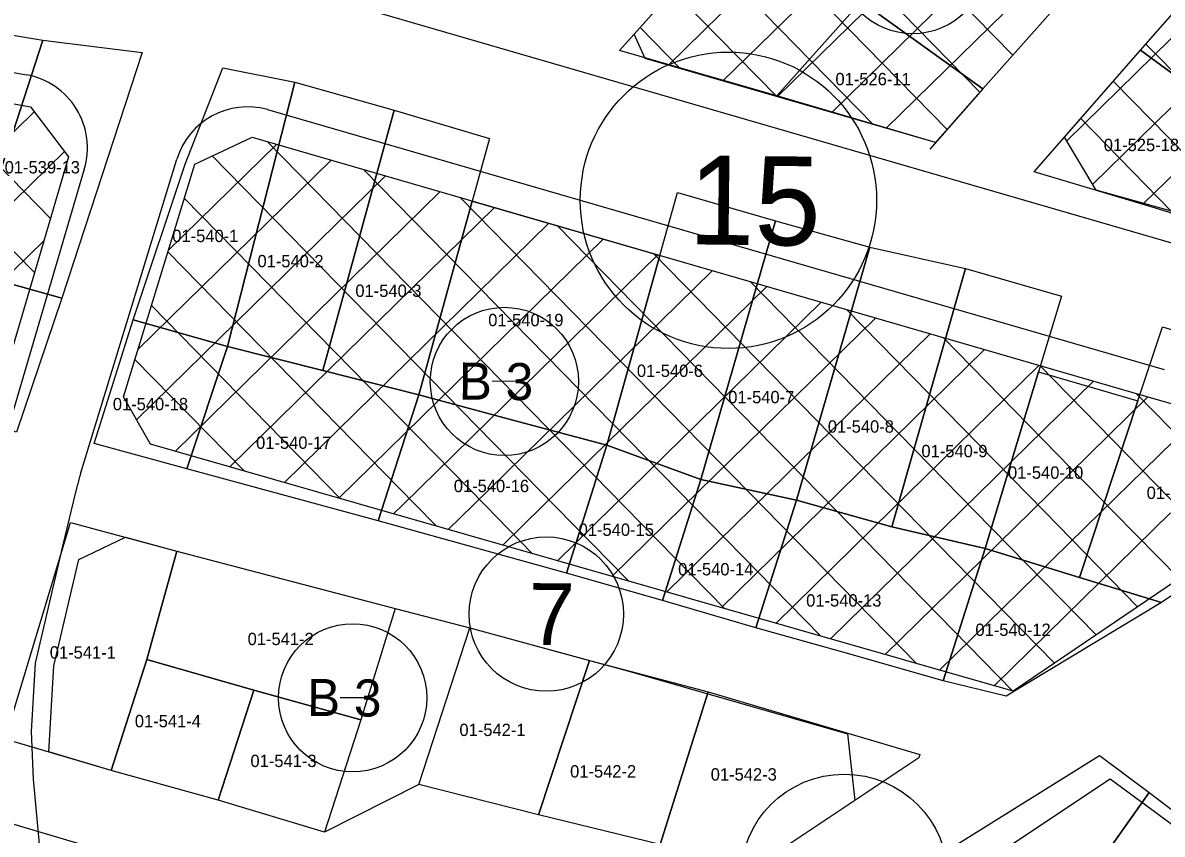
# Model space of a CAD drawing. Extents: x 413946 to 415528, y 4453939 to 4454944.
# Drawn here: x 415176.9 to 415269.2, y 4454344.2 to 4454409.9 of the extents above; entities that cross this region are included whole.
import ezdxf

# ---------------------------------------------------------------- set-up
doc = ezdxf.new("R2010")
doc.units = 0
for name, color, linetype in [('0_KADASTRO', 7, 'Continuous'), ('Level 27', 7, 'Continuous'), ('Level 28', 7, 'Continuous'), ('Level 29', 7, 'Continuous'), ('Level 32', 7, 'Continuous'), ('Level 34', 7, 'Continuous'), ('Level 58', 7, 'Continuous'), ('Level 62', 7, 'Continuous')]:
    doc.layers.add(name, color=color, linetype=linetype)

msp = doc.modelspace()

# ---------------------------------------------------------------- linework, layer by layer
at = {"layer": '0_KADASTRO'}
for points in [[(415225.23, 4454407.64), (415234.94, 4454418.45), (415244.8, 4454411.6), (415237.99, 4454403.96)], [(415244.8, 4454411.6), (415251.43, 4454419.09), (415251.62, 4454419.3), (415261.25, 4454411.96), (415254.68, 4454404.53)], [(415267.45, 4454407.66), (415274.07, 4454415.22), (415283.75, 4454408.21), (415280.79, 4454405.04), (415279.76, 4454403.95), (415277.28, 4454400.45), (415274.74, 4454402.31)], [(415237.99, 4454403.96), (415244.8, 4454411.6), (415254.68, 4454404.53), (415250.84, 4454400.18)], [(415164.81, 4454392.51), (415170.55, 4454409.79), (415178.51, 4454408.47), (415172.41, 4454389.72)], [(415172.41, 4454389.72), (415178.51, 4454408.47), (415186.56, 4454407.48), (415180.05, 4454387.58)], [(415258.83, 4454397.82), (415267.45, 4454407.66), (415274.74, 4454402.31), (415277.28, 4454400.45), (415274.26, 4454396.92), (415271.72, 4454393.93), (415268.37, 4454394.95)], [(415185.83, 4454385.83), (415190.04, 4454398.42), (415193.1, 4454406.23), (415198.93, 4454405.07), (415193.48, 4454383.68)], [(415193.48, 4454383.68), (415198.93, 4454405.07), (415206.97, 4454402.8), (415201.2, 4454381.72)], [(415201.2, 4454381.72), (415206.97, 4454402.8), (415214.7, 4454400.5), (415213.302, 4454395.439), (415208.97, 4454379.75)], [(415208.97, 4454379.75), (415213.302, 4454395.439), (415220.87, 4454393.25), (415228.514, 4454391.039), (415224.21, 4454375.67), (415216.6, 4454377.69)], [(415224.21, 4454375.67), (415228.514, 4454391.039), (415229.94, 4454396.13), (415237.87, 4454393.84), (415231.83, 4454372.91)], [(415231.83, 4454372.91), (415237.87, 4454393.84), (415245.51, 4454391.7), (415239.56, 4454371.23)], [(415239.56, 4454371.23), (415245.51, 4454391.7), (415253.27, 4454389.97), (415247.29, 4454369.07)], [(415247.29, 4454369.07), (415253.27, 4454389.97), (415261.03, 4454387.75), (415259.18, 4454381.61), (415254.85, 4454367.31)], [(415168.83, 4454378.8), (415172.41, 4454389.72), (415180.05, 4454387.58), (415176.39, 4454376.74)], [(415182.67, 4454375.82), (415185.83, 4454385.83), (415193.48, 4454383.68), (415190.2, 4454373.75)], [(415262.5, 4454364.97), (415267.23, 4454379.26), (415269.22, 4454385.27), (415282.582, 4454381.146), (415285.81, 4454380.15), (415289.82, 4454376.75), (415276.237, 4454367.69), (415269.13, 4454362.95)], [(415190.2, 4454373.75), (415193.48, 4454383.68), (415201.2, 4454381.72), (415208.97, 4454379.75), (415205.69, 4454369.54)], [(415254.85, 4454367.31), (415259.18, 4454381.61), (415267.23, 4454379.26), (415262.5, 4454364.97)], [(415205.69, 4454369.54), (415208.97, 4454379.75), (415216.6, 4454377.69), (415224.21, 4454375.67), (415220.95, 4454365.32)], [(415220.95, 4454365.32), (415224.21, 4454375.67), (415231.83, 4454372.91), (415228.73, 4454363.11)], [(415228.73, 4454363.11), (415231.83, 4454372.91), (415239.56, 4454371.23), (415236.29, 4454360.89)], [(415236.29, 4454360.89), (415239.56, 4454371.23), (415247.29, 4454369.07), (415254.85, 4454367.31), (415251.46, 4454356.59), (415244.01, 4454358.74)], [(415175.48, 4454351.88), (415180.77, 4454369.43), (415189.39, 4454367.1), (415186.95, 4454358.32), (415184.05, 4454349.35)], [(415186.95, 4454358.32), (415189.39, 4454367.1), (415207.06, 4454362.45), (415204.29, 4454353.43), (415195.61, 4454355.85)], [(415251.46, 4454356.59), (415254.85, 4454367.31), (415262.5, 4454364.97), (415269.13, 4454362.95), (415256.56, 4454355.35)], [(415208.98, 4454348.2), (415213.12, 4454360.9), (415222.81, 4454358.25), (415218.68, 4454345.75)], [(415184.05, 4454349.35), (415186.95, 4454358.32), (415195.61, 4454355.85), (415192.72, 4454346.93)], [(415218.68, 4454345.75), (415222.81, 4454358.25), (415232.41, 4454355.7), (415228.54, 4454343.35)], [(415192.72, 4454346.93), (415195.61, 4454355.85), (415204.29, 4454353.43), (415201.34, 4454344.36)], [(415228.54, 4454343.35), (415232.41, 4454355.7), (415249.56, 4454350.64), (415249.48, 4454350.36), (415234.67, 4454340.5)], [(415250.984, 4454342.38), (415264.123, 4454350.547), (415264.2, 4454350.49), (415268.14, 4454347.57), (415265.14, 4454343.31), (415263.86, 4454341.48), (415262.46, 4454339.35), (415259.73, 4454335.58), (415258.68, 4454336.397), (415251.73, 4454341.8)], [(415259.73, 4454335.58), (415262.46, 4454339.35), (415263.86, 4454341.48), (415265.14, 4454343.31), (415268.14, 4454347.57), (415275.96, 4454341.63), (415271.42, 4454334.96), (415270.31, 4454333.38), (415267.64, 4454329.34), (415265.69, 4454330.906), (415263.32, 4454332.81)], [(415170.03, 4454333.38), (415173.69, 4454345.73), (415181.44, 4454343.44), (415177.6, 4454331.01), (415171.68, 4454332.9)]]:
    msp.add_lwpolyline(points, close=True, dxfattribs=at)
at = {"layer": 'Level 27'}
for p, q in [((415204.089, 4454370.927), (415187.252, 4454375.747)), ((415204.09, 4454370.927), (415204.089, 4454370.927)), ((415204.092, 4454370.927), (415204.091, 4454370.927)), ((415257.121, 4454355.751), (415204.092, 4454370.927))]:
    msp.add_line(p, q, dxfattribs=at)
for points in [[(415226.413, 4454408.957), (415234.94, 4454418.45), (415241.61, 4454426.04), (415248.27, 4454433.38), (415254.93, 4454441.05), (415261.53, 4454448.35), (415268.31, 4454455.75), (415274.51, 4454462.72), (415280.65, 4454469.3), (415288.33, 4454477.82), (415292.88, 4454482.84)], [(415310.574, 4454466.789), (415305.2, 4454460.96), (415299.8, 4454455.11), (415293.06, 4454447.82), (415287.9, 4454441.92), (415281.11, 4454434.3), (415274.64, 4454426.85), (415267.96, 4454419.45), (415261.25, 4454411.96), (415254.68, 4454404.53), (415250.364, 4454399.64)], [(415261.285, 4454400.622), (415267.45, 4454407.66), (415274.07, 4454415.22), (415280.63, 4454422.65), (415287.22, 4454430.12), (415292.45, 4454436.24), (415293.926, 4454437.825), (415294.498, 4454437.407), (415302.032, 4454445.623), (415316.534, 4454461.44)], [(415185.225, 4454368.226), (415189.39, 4454367.1), (415207.06, 4454362.45), (415213.12, 4454360.9), (415226.002, 4454357.377)], [(415201.34, 4454344.36), (415192.72, 4454346.93), (415184.05, 4454349.35), (415178.995, 4454350.842)], [(415264.984, 4454348.669), (415274.805, 4454341.419), (415313.615, 4454312.821), (415331.254, 4454309.711), (415373.854, 4454288.964), (415353.123, 4454256.024)], [(415234.67, 4454340.5), (415228.54, 4454343.35), (415218.68, 4454345.75), (415208.98, 4454348.2)]]:
    msp.add_lwpolyline(points, dxfattribs=at)
at = {"layer": 'Level 28'}
msp.add_line((415278.268, 4454370.094), (415257.121, 4454355.751), dxfattribs=at)
for points in [[(415250.84, 4454400.18), (415227.323, 4454406.996), (415226.413, 4454408.957)], [(415195.475, 4454400.608), (415268.668, 4454379.396)], [(415284.734, 4454390.491), (415263.836, 4454396.314), (415261.285, 4454400.622)], [(415187.252, 4454375.747), (415185.051, 4454379.589), (415190.823, 4454398.431)], [(415268.668, 4454379.396), (415279.451, 4454376.391)], [(415178.995, 4454350.842), (415179.408, 4454357.806), (415181.446, 4454366.435), (415185.225, 4454368.226)], [(415243.716, 4454352.307), (415244.306, 4454346.915)], [(415242.176, 4454333.483), (415264.984, 4454348.669)]]:
    msp.add_lwpolyline(points, dxfattribs=at)
at = {"layer": 'Level 29'}
for p, q in [((415177.519, 4454403.064), (415180.61, 4454399.019)), ((415190.823, 4454398.431), (415195.475, 4454400.608)), ((415226.002, 4454357.377), (415243.716, 4454352.307)), ((415208.98, 4454348.2), (415201.34, 4454344.36))]:
    msp.add_line(p, q, dxfattribs=at)
for points in [[(415078.7, 4454427.908), (415121.68, 4454415.05), (415144.9, 4454408.93), (415177.519, 4454403.064)], [(415180.61, 4454399.019), (415173.461, 4454374.818), (415172.452, 4454371.283)], [(415244.306, 4454346.915), (415234.67, 4454340.5)]]:
    msp.add_lwpolyline(points, dxfattribs=at)
at = {"layer": 'Level 32'}
for p, q in [((415216.91, 4454380.829), (415214.91, 4454380.85)), ((415204.62, 4454355.215), (415202.62, 4454355.235))]:
    msp.add_line(p, q, dxfattribs=at)
for centre in [(415248.986, 4454414.989), (415215.91, 4454380.84), (415203.62, 4454355.225)]:
    msp.add_circle(centre, 6, dxfattribs=at)
at = {"layer": 'Level 34'}
for p, q in [((415229.199, 4454406.452), (415253.156, 4454429.923)), ((415233.61, 4454405.174), (415256.475, 4454427.575)), ((415238.021, 4454403.895), (415259.794, 4454425.227)), ((415257.092, 4454407.258), (415240.229, 4454424.469)), ((415242.432, 4454402.617), (415263.113, 4454422.879)), ((415254.436, 4454404.253), (415237.581, 4454421.456)), ((415246.843, 4454401.339), (415266.432, 4454420.531)), ((415261.458, 4454400.33), (415282.722, 4454421.164)), ((415251.781, 4454401.247), (415234.933, 4454418.443)), ((415263.556, 4454396.786), (415286.036, 4454418.81)), ((415267.693, 4454395.239), (415289.349, 4454416.457)), ((415245.793, 4454401.643), (415232.255, 4454415.461)), ((415237.973, 4454403.909), (415229.577, 4454412.479)), ((415230.152, 4454406.176), (415226.898, 4454409.497)), ((415284.946, 4454390.737), (415267.882, 4454408.154)), ((415177.843, 4454389.651), (415161.96, 4454405.862)), ((415179.14, 4454394.043), (415168.757, 4454404.639)), ((415277.655, 4454392.464), (415265.239, 4454405.136)), ((415154.868, 4454380.177), (415177.823, 4454402.666)), ((415269.952, 4454394.61), (415262.596, 4454402.118)), ((415188.678, 4454391.429), (415197.46, 4454400.033)), ((415225.678, 4454370.685), (415196.712, 4454400.249)), ((415159.284, 4454378.905), (415180.269, 4454399.465)), ((415220.017, 4454370.748), (415192.242, 4454399.095)), ((415186.227, 4454383.428), (415201.87, 4454398.755)), ((415186.12, 4454377.723), (415206.282, 4454397.477)), ((415231.341, 4454370.621), (415204.532, 4454397.984)), ((415189.238, 4454375.179), (415210.692, 4454396.198)), ((415214.354, 4454370.812), (415189.982, 4454395.686)), ((415237.003, 4454370.557), (415212.353, 4454395.717)), ((415193.662, 4454373.913), (415215.103, 4454394.92)), ((415198.085, 4454372.647), (415219.514, 4454393.642)), ((415242.665, 4454370.494), (415220.173, 4454393.451)), ((415163.701, 4454377.633), (415178.606, 4454392.235)), ((415202.509, 4454371.381), (415223.925, 4454392.363)), ((415208.692, 4454370.876), (415188.649, 4454391.333)), ((415207.72, 4454370.887), (415228.336, 4454391.085)), ((415248.328, 4454370.43), (415227.994, 4454391.184)), ((415213.371, 4454370.823), (415232.747, 4454389.807)), ((415253.99, 4454370.367), (415235.814, 4454388.918)), ((415219.021, 4454370.76), (415237.157, 4454388.528)), ((415224.672, 4454370.696), (415241.568, 4454387.25)), ((415202.632, 4454371.345), (415187.315, 4454386.979)), ((415259.652, 4454370.303), (415243.635, 4454386.651)), ((415230.323, 4454370.633), (415245.979, 4454385.972)), ((415235.974, 4454370.569), (415250.39, 4454384.693)), ((415265.314, 4454370.239), (415251.455, 4454384.385)), ((415241.625, 4454370.506), (415254.801, 4454383.415)), ((415194.85, 4454373.573), (415185.981, 4454382.625)), ((415247.275, 4454370.442), (415259.212, 4454382.137)), ((415270.977, 4454370.176), (415259.276, 4454382.118)), ((415252.927, 4454370.378), (415263.623, 4454380.858)), ((415276.639, 4454370.112), (415267.096, 4454379.851)), ((415258.577, 4454370.315), (415268.033, 4454379.58)), ((415264.228, 4454370.251), (415272.478, 4454378.334)), ((415206.932, 4454370.115), (415207.72, 4454370.887)), ((415207.72, 4454370.887), (415207.72, 4454370.887)), ((415207.72, 4454370.887), (415207.72, 4454370.887)), ((415207.72, 4454370.887), (415207.72, 4454370.887)), ((415208.692, 4454370.876), (415208.692, 4454370.876)), ((415208.692, 4454370.876), (415208.692, 4454370.876)), ((415208.692, 4454370.876), (415208.692, 4454370.876)), ((415210.414, 4454369.118), (415208.692, 4454370.876)), ((415211.356, 4454368.849), (415213.371, 4454370.823)), ((415218.196, 4454366.891), (415214.354, 4454370.812)), ((415215.779, 4454367.583), (415219.021, 4454370.76)), ((415219.021, 4454370.76), (415219.021, 4454370.76)), ((415219.021, 4454370.76), (415219.021, 4454370.76)), ((415219.021, 4454370.76), (415219.021, 4454370.76)), ((415220.017, 4454370.748), (415220.017, 4454370.748)), ((415220.017, 4454370.748), (415220.017, 4454370.748)), ((415225.978, 4454364.664), (415220.017, 4454370.748)), ((415220.203, 4454366.317), (415224.672, 4454370.696)), ((415224.626, 4454365.051), (415230.323, 4454370.633)), ((415233.759, 4454362.437), (415225.678, 4454370.685)), ((415229.05, 4454363.785), (415235.974, 4454370.569)), ((415230.323, 4454370.633), (415230.323, 4454370.633)), ((415230.323, 4454370.633), (415230.323, 4454370.633)), ((415230.323, 4454370.633), (415230.323, 4454370.633)), ((415241.541, 4454360.21), (415231.341, 4454370.621)), ((415233.473, 4454362.519), (415241.625, 4454370.506)), ((415237.003, 4454370.557), (415237.003, 4454370.557)), ((415237.003, 4454370.557), (415237.003, 4454370.557)), ((415249.323, 4454357.983), (415237.003, 4454370.557)), ((415237.896, 4454361.253), (415247.275, 4454370.442)), ((415241.625, 4454370.506), (415241.625, 4454370.506)), ((415241.625, 4454370.506), (415241.625, 4454370.506)), ((415241.625, 4454370.506), (415241.625, 4454370.506)), ((415257.105, 4454355.756), (415242.665, 4454370.494)), ((415260.479, 4454358.028), (415248.328, 4454370.43)), ((415242.32, 4454359.987), (415252.927, 4454370.378)), ((415246.743, 4454358.721), (415258.577, 4454370.315)), ((415251.167, 4454357.455), (415264.228, 4454370.251)), ((415252.927, 4454370.378), (415252.927, 4454370.378)), ((415252.927, 4454370.378), (415252.927, 4454370.378)), ((415253.99, 4454370.367), (415253.99, 4454370.367)), ((415253.99, 4454370.367), (415253.99, 4454370.367)), ((415253.99, 4454370.367), (415253.99, 4454370.367)), ((415263.843, 4454360.31), (415253.99, 4454370.367)), ((415255.59, 4454356.189), (415269.879, 4454370.188)), ((415267.207, 4454362.591), (415259.652, 4454370.303)), ((415264.228, 4454370.251), (415264.228, 4454370.251)), ((415264.228, 4454370.251), (415264.228, 4454370.251)), ((415265.314, 4454370.239), (415265.314, 4454370.239)), ((415265.314, 4454370.239), (415265.314, 4454370.239)), ((415270.572, 4454364.873), (415265.314, 4454370.239))]:
    msp.add_line(p, q, dxfattribs=at)
at = {"layer": 'Level 58'}
for centre, radius in [((415234.061, 4454395.507), 12), ((415219.305, 4454362.001), 6.25), ((415243.441, 4454340.644), 8.4)]:
    msp.add_circle(centre, radius, dxfattribs=at)
at = {"layer": 'Level 62'}
for points in [[(415078.403, 4454430.606), (415122.357, 4454417.457), (415145.441, 4454411.373), (415177.198, 4454405.661)], [(415272.017, 4454391.439), (415205.951, 4454410.588)], [(415196.73, 4454402.847), (415269.364, 4454381.797)], [(415181.573, 4454373.36), (415189.376, 4454398.826)], [(415181.882, 4454398.028), (415174.902, 4454374.4), (415174.008, 4454371.266)], [(415181.027, 4454371.187), (415181.317, 4454372.413)], [(415180.155, 4454367.496), (415181.027, 4454371.187)], [(415181.027, 4454371.187), (415181.027, 4454371.187)], [(415181.027, 4454371.187), (415181.027, 4454371.187)], [(415181.027, 4454371.187), (415181.027, 4454371.187)], [(415180.986, 4454313.841), (415177.768, 4454348.634), (415177.591, 4454352.499), (415177.918, 4454358.024), (415180.155, 4454367.496)]]:
    msp.add_lwpolyline(points, dxfattribs=at)
for centre, radius, start, end in [((415176.136, 4454399.755), 6, 343.26749, 79.80367), ((415195.113, 4454397.068), 6, 74.36928, 162.96484), ((415195.915, 4454368.965), 15, 162.96406, 166.71121)]:
    msp.add_arc(centre, radius, start, end, dxfattribs=at)

# ---------------------------------------------------------------- texts
at = {"layer": '0_KADASTRO'}
for s, p in [('01-526-11', (415242.726, 4454404.819)), ('01-525-18', (415264.462, 4454399.485)), ('01-539-13', (415175.432, 4454397.681)), ('01-540-1', (415189.01, 4454392.121)), ('01-540-2', (415195.909, 4454390.08)), ('01-540-3', (415203.839, 4454387.68)), ('01-540-19', (415214.6, 4454385.31)), ('01-540-6', (415226.643, 4454381.2)), ('01-540-7', (415234.042, 4454379.07)), ('01-540-18', (415184.19, 4454378.502)), ('01-540-8', (415242.109, 4454376.69)), ('01-540-17', (415195.797, 4454375.379)), ('01-540-9', (415249.693, 4454374.7)), ('01-540-10', (415256.706, 4454372.96)), ('01-540-16', (415211.812, 4454371.874)), ('01-540-11', (415267.938, 4454371.32)), ('01-540-15', (415221.925, 4454368.335)), ('01-540-14', (415229.983, 4454365.135)), ('01-540-13', (415240.356, 4454362.609)), ('01-540-12', (415254.065, 4454360.231)), ('01-541-2', (415195.113, 4454359.489)), ('01-541-1', (415179.084, 4454358.4)), ('01-541-4', (415185.975, 4454352.84)), ('01-542-1', (415212.268, 4454352.129)), ('01-541-3', (415195.34, 4454349.619)), ('01-542-2', (415221.233, 4454348.771)), ('01-542-3', (415232.625, 4454348.524))]:
    msp.add_text(s, height=1, dxfattribs=at).set_placement(p)
at = {"layer": 'Level 32'}
for p in [(415212.21, 4454379.377), (415199.92, 4454353.763)]:
    msp.add_text('B 3', height=3, rotation=359.4141, dxfattribs=at).set_placement(p)
at = {"layer": 'Level 58'}
for s, height, p in [('15', 7.2, (415230.794, 4454391.94)), ('7', 5, (415217.862, 4454359.516))]:
    msp.add_text(s, height=height, rotation=359.4141, dxfattribs=at).set_placement(p)

doc.saveas('drawing.dxf')
